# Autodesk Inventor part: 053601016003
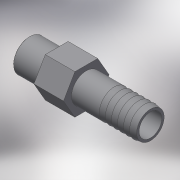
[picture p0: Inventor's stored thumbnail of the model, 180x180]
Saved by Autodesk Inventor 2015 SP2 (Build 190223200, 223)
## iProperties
Created: 2017-10
Part Number: 053601016003
Material: Generic
Description: PLASSON THREADED HOSE NOZZLE 3/8"-16
Document SubType Name: Modeling
Designer: KIM
Density: 1 g/cm^3
Appearance: Default
Author: KIM
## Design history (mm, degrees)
derived "053601.ipt"
feature "Solid1::053601.ipt"
tag "TaggingFeature1"
body "Solid1"
other parameters: "d0" = 58, "d1" = 170 deg, "d2" = 16, "d6" = 11.6634, "d8" = 17.4, "d9" = 16.662, "d10" = 22, "d11" = 13, "d12" = 12, "d13" = 12, "d14" = 0, "d15" = 0.12, "d_" = 12, "E_" = 16, "H_" = 58, "R_" = 16.662, "C_" = 22, "B_" = 12, "Lt_" = 13
